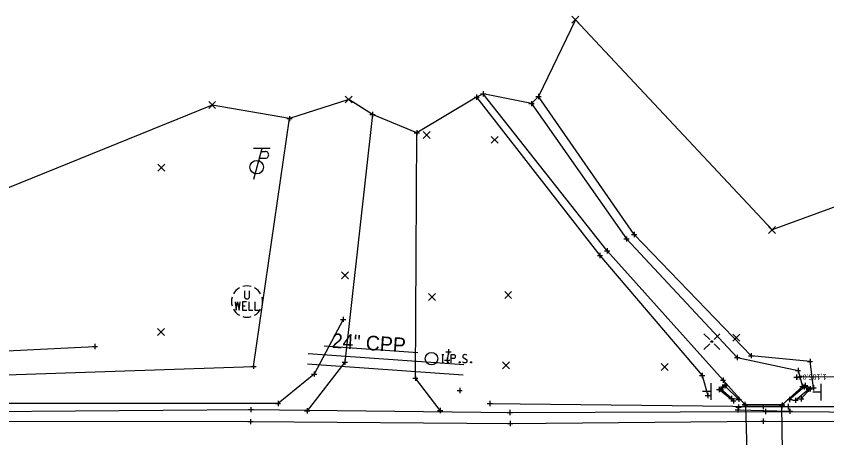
# Model space of a CAD drawing. Extents: x 2319153 to 2321514, y 575338 to 575500.
# Drawn here: x 2320670.1 to 2320825.9, y 575419.3 to 575500.3 of the extents above; entities that cross this region are included whole.
import ezdxf

# ---------------------------------------------------------------- set-up
doc = ezdxf.new("R2010")
doc.units = 0
for name, color, linetype in [('DR_X_Culvert', 7, 'Continuous'), ('DR_X_Ditch', 7, 'Continuous'), ('DR_X_Elev_Flow', 7, 'Continuous'), ('DR_X_Headwall', 7, 'Continuous'), ('DR_X_Storm_Sewer', 7, 'Continuous'), ('DR_X_Text', 7, 'Continuous'), ('PV_X_Driveway', 7, 'Continuous'), ('PV_X_EOP', 7, 'Continuous'), ('PV_X_Shoulder', 7, 'Continuous'), ('RD_X_GR_Lt', 7, 'Continuous'), ('RD_X_Wall', 7, 'Continuous'), ('SC_Scratch1', 7, 'Continuous'), ('SN_X_Public', 7, 'Continuous'), ('SV_P_Mon_Cells_Set', 7, 'Continuous'), ('SV_X_Break_Lines', 7, 'Continuous'), ('SV_X_Control_Cells_Found', 7, 'Continuous'), ('SV_X_Random_Point', 7, 'Continuous'), ('SV_X_Shot_Marker', 7, 'Continuous'), ('SV_X_Terrain_Boundary', 7, 'Continuous'), ('UT_X_Misc_Cells', 7, 'Continuous'), ('UT_X_Unknown_Cells', 7, 'Continuous')]:
    doc.layers.add(name, color=color, linetype=linetype)

msp = doc.modelspace()

# ---------------------------------------------------------------- linework, layer by layer
at = {"layer": 'DR_X_Culvert'}
msp.add_lwpolyline([(2320811.09, 575399.31), (2320817.7, 575399.29), (2320817.26, 575425.4), (2320810.29, 575425.41)], close=True, dxfattribs=at)
at = {"layer": 'DR_X_Ditch'}
for points in [[(2320769.15, 575483.51), (2320787.4, 575457.5), (2320808.68, 575434.74), (2320820.4, 575432.23), (2320821.28, 575429.18), (2320817.36, 575425.61), (2320810.18, 575425.69), (2320805.98, 575430.37), (2320783.69, 575455.23), (2320759.85, 575485.4)], [(2320442.27, 575427.97), (2320464.89, 575430.3), (2320567.27, 575429.23), (2320616.67, 575430.56), (2320664.25, 575431.29), (2320715.69, 575433.03), (2320722.62, 575480.62)]]:
    msp.add_lwpolyline(points, dxfattribs=at)
at = {"layer": 'DR_X_Elev_Flow'}
for p, q in [((2320820.1, 575431.46), (2320820.1, 575430.46)), ((2320819.6, 575430.96), (2320820.6, 575430.96)), ((2320820.1, 575430.96), (2320820.1, 575430.96))]:
    msp.add_line(p, q, dxfattribs=at)
at = {"layer": 'DR_X_Headwall'}
msp.add_lwpolyline([(2320808.96, 575425.17), (2320808.8, 575424.69), (2320818.83, 575424.39), (2320818.53, 575425.31)], close=True, dxfattribs=at)
at = {"layer": 'DR_X_Storm_Sewer'}
for p, q in [((2320756.14, 575433.31), (2320726.22, 575435.45)), ((2320756, 575431.31), (2320726.08, 575433.46)), ((2320984.73, 575431.64), (2320820.1, 575430.96))]:
    msp.add_line(p, q, dxfattribs=at)
at = {"layer": 'DR_X_Text'}
msp.add_line((2320747.27, 575435.6), (2320729.26, 575436.89), dxfattribs=at)
at = {"layer": 'PV_X_Driveway'}
for points in [[(2320738.56, 575481.4), (2320733.25, 575433.83), (2320725.99, 575424.49)], [(2320751.57, 575424.54), (2320746.81, 575430.73), (2320747.1, 575477.92)]]:
    msp.add_lwpolyline(points, dxfattribs=at)
at = {"layer": 'PV_X_EOP'}
msp.add_lwpolyline([(2320664.7, 575422.48), (2320715.11, 575422.41), (2320765.04, 575422.04), (2320813.73, 575422.51), (2320875.77, 575422.41), (2320913.27, 575422.56), (2320963.52, 575422.63), (2321012.62, 575422.4), (2321063.13, 575422.74), (2321112.87, 575422.46), (2321162.94, 575422.5), (2321212.67, 575422.22), (2321263.07, 575422.64), (2321312.9, 575422.52), (2321362.03, 575422.99), (2321412.61, 575423.24), (2321462.61, 575423.66), (2321512.13, 575424.2)], dxfattribs=at)
at = {"layer": 'PV_X_Shoulder'}
msp.add_lwpolyline([(2320664.52, 575424.33), (2320715.19, 575424.71), (2320764.98, 575424.15), (2320814.14, 575424.35), (2320863.42, 575424.12), (2320913.2, 575424.6), (2320963.28, 575424.88), (2321012.77, 575424.72), (2321063.18, 575424.45), (2321113.13, 575424.68), (2321162.73, 575424.41), (2321212.81, 575424.31), (2321262.9, 575424.09), (2321312.43, 575424.58), (2321362.34, 575425.06), (2321412.6, 575426.1), (2321462.14, 575426.29), (2321512.24, 575426.46)], dxfattribs=at)
at = {"layer": 'RD_X_GR_Lt'}
for p, q in [((2320753.17, 575435.82), (2320752.92, 575434.24)), ((2320761.13, 575425.9), (2320813.7, 575425.29)), ((2320813.7, 575425.29), (2320879.64, 575425.43))]:
    msp.add_line(p, q, dxfattribs=at)
at = {"layer": 'RD_X_Wall'}
for points in [[(2320809.02, 575426.68), (2320807.6, 575426.85), (2320805.56, 575428.66), (2320806.3, 575429.26)], [(2320818.79, 575426.67), (2320819.93, 575426.51), (2320822.44, 575428.64), (2320821.58, 575429.06)]]:
    msp.add_lwpolyline(points, close=True, dxfattribs=at)
at = {"layer": 'SN_X_Public'}
for p, q in [((2320803.63, 575429.77), (2320803.63, 575426.57)), ((2320824.82, 575429.65), (2320824.82, 575426.45)), ((2320803.63, 575428.17), (2320802.03, 575428.17)), ((2320824.82, 575428.05), (2320823.22, 575428.05))]:
    msp.add_line(p, q, dxfattribs=at)
at = {"layer": 'SV_P_Mon_Cells_Set'}
for points in [[(2320751.93, 575435.29), (2320752.28, 575435.29)], [(2320752.1, 575433.69), (2320752.1, 575435.29)], [(2320753.67, 575433.69), (2320753.67, 575435.29), (2320754.2, 575435.29), (2320754.25, 575435.28), (2320754.33, 575435.25), (2320754.36, 575435.23), (2320754.4, 575435.2), (2320754.44, 575435.14), (2320754.47, 575435.07), (2320754.5, 575434.97), (2320754.5, 575434.82), (2320754.49, 575434.77), (2320754.46, 575434.7), (2320754.42, 575434.61), (2320754.38, 575434.57), (2320754.34, 575434.55), (2320754.29, 575434.52), (2320754.2, 575434.51), (2320753.67, 575434.51)], [(2320756.68, 575435.18), (2320756.66, 575435.2), (2320756.62, 575435.23), (2320756.53, 575435.26), (2320756.4, 575435.29), (2320756.32, 575435.29), (2320756.28, 575435.29), (2320756.14, 575435.25), (2320756.02, 575435.18), (2320755.94, 575435.07), (2320755.92, 575434.97), (2320755.92, 575434.9), (2320755.94, 575434.8), (2320756.03, 575434.71), (2320756.64, 575434.33), (2320756.69, 575434.28), (2320756.71, 575434.23), (2320756.73, 575434.15), (2320756.73, 575434.08), (2320756.72, 575434), (2320756.71, 575433.95), (2320756.69, 575433.89), (2320756.67, 575433.84), (2320756.65, 575433.8), (2320756.61, 575433.76), (2320756.58, 575433.74), (2320756.54, 575433.71), (2320756.5, 575433.7), (2320756.4, 575433.69), (2320756.25, 575433.69), (2320756.15, 575433.71), (2320756.01, 575433.8), (2320755.92, 575433.88)], [(2320751.93, 575433.69), (2320752.28, 575433.69)], [(2320753.06, 575433.9), (2320753.12, 575433.9), (2320753.15, 575433.88), (2320753.19, 575433.83), (2320753.19, 575433.76), (2320753.15, 575433.71), (2320753.12, 575433.69), (2320753.06, 575433.69), (2320753.03, 575433.71), (2320753, 575433.76), (2320753, 575433.83), (2320753.03, 575433.88), (2320753.06, 575433.9)], [(2320755.31, 575433.9), (2320755.37, 575433.9), (2320755.4, 575433.88), (2320755.43, 575433.83), (2320755.43, 575433.76), (2320755.4, 575433.71), (2320755.37, 575433.69), (2320755.31, 575433.69), (2320755.28, 575433.71), (2320755.25, 575433.76), (2320755.25, 575433.83), (2320755.28, 575433.88), (2320755.31, 575433.9)], [(2320757.5, 575433.9), (2320757.55, 575433.9), (2320757.58, 575433.88), (2320757.62, 575433.83), (2320757.62, 575433.76), (2320757.58, 575433.71), (2320757.55, 575433.69), (2320757.5, 575433.69), (2320757.46, 575433.71), (2320757.43, 575433.76), (2320757.43, 575433.83), (2320757.46, 575433.88), (2320757.5, 575433.9)]]:
    msp.add_lwpolyline(points, dxfattribs=at)
msp.add_circle((2320749.91, 575434.49), 1.2, dxfattribs=at)
at = {"layer": 'SV_X_Break_Lines'}
for points in [[(2320758.6, 575484.73), (2320782.31, 575454.32), (2320801.95, 575431.28), (2320803.03, 575427.42)], [(2320823.37, 575428.92), (2320822.71, 575433.99), (2320811.41, 575435.08), (2320788.91, 575458.37), (2320770.49, 575484.86)], [(2320732.93, 575442.06), (2320727.34, 575431.55), (2320720.41, 575425.89), (2320664.7, 575425.9), (2320613.83, 575426.05), (2320563.12, 575426.93), (2320514.6, 575426.5), (2320463.64, 575427.26), (2320441.18, 575426.16), (2320442.02, 575430.24), (2320514.44, 575433.22), (2320564.58, 575433.19), (2320614.81, 575433.37), (2320685.2, 575436.83)], [(2320806.3, 575429.48), (2320805.21, 575428.58), (2320807.97, 575426.4)], [(2320821.01, 575426.77), (2320822.71, 575428.71), (2320821.78, 575429.37)]]:
    msp.add_lwpolyline(points, dxfattribs=at)
at = {"layer": 'SV_X_Control_Cells_Found'}
for p, q in [((2320802.32, 575439.28), (2320803.42, 575438.19)), ((2320804.25, 575438.19), (2320805.34, 575439.28)), ((2320802.32, 575436.26), (2320803.42, 575437.36)), ((2320804.25, 575437.36), (2320805.34, 575436.26))]:
    msp.add_line(p, q, dxfattribs=at)
msp.add_circle((2320803.83, 575437.78), 0.17, dxfattribs=at)
at = {"layer": 'SV_X_Random_Point'}
for p, q in [((2320776.92, 575498.97), (2320778.26, 575500.3)), ((2320776.92, 575500.3), (2320778.26, 575498.97)), ((2320733.34, 575483.63), (2320734.67, 575484.97)), ((2320733.34, 575484.97), (2320734.67, 575483.63)), ((2320707.07, 575482.57), (2320708.4, 575483.91)), ((2320707.07, 575483.91), (2320708.4, 575482.57)), ((2320748.33, 575476.81), (2320749.67, 575478.14)), ((2320748.33, 575478.14), (2320749.67, 575476.81)), ((2320761.39, 575475.88), (2320762.72, 575477.22)), ((2320761.39, 575477.22), (2320762.72, 575475.88)), ((2320697.32, 575470.53), (2320698.66, 575471.86)), ((2320697.32, 575471.86), (2320698.66, 575470.53)), ((2320814.75, 575458.56), (2320816.08, 575459.89)), ((2320814.75, 575459.89), (2320816.08, 575458.56)), ((2320732.61, 575449.83), (2320733.94, 575451.16)), ((2320732.61, 575451.16), (2320733.94, 575449.83)), ((2320749.37, 575445.67), (2320750.7, 575447.01)), ((2320749.37, 575447.01), (2320750.7, 575445.67)), ((2320763.99, 575446.05), (2320765.32, 575447.38)), ((2320763.99, 575447.38), (2320765.32, 575446.05)), ((2320697.23, 575438.96), (2320698.57, 575440.3)), ((2320697.23, 575440.3), (2320698.57, 575438.96)), ((2320807.87, 575437.88), (2320809.21, 575439.21)), ((2320807.87, 575439.21), (2320809.21, 575437.88)), ((2320763.59, 575432.58), (2320764.92, 575433.92)), ((2320763.59, 575433.92), (2320764.92, 575432.58)), ((2320794.08, 575432.23), (2320795.41, 575433.56)), ((2320794.08, 575433.56), (2320795.41, 575432.23))]:
    msp.add_line(p, q, dxfattribs=at)
at = {"layer": 'SV_X_Shot_Marker'}
for p, q in [((2320759.85, 575485.9), (2320759.85, 575484.9)), ((2320758.1, 575484.73), (2320759.1, 575484.73)), ((2320758.6, 575485.23), (2320758.6, 575484.23)), ((2320758.6, 575484.73), (2320758.6, 575484.73)), ((2320759.35, 575485.4), (2320760.35, 575485.4)), ((2320759.85, 575485.4), (2320759.85, 575485.4)), ((2320769.99, 575484.86), (2320770.99, 575484.86)), ((2320770.49, 575485.36), (2320770.49, 575484.36)), ((2320770.49, 575484.86), (2320770.49, 575484.86)), ((2320768.65, 575483.51), (2320769.65, 575483.51)), ((2320769.15, 575484.01), (2320769.15, 575483.01)), ((2320769.15, 575483.51), (2320769.15, 575483.51)), ((2320722.62, 575481.12), (2320722.62, 575480.12)), ((2320738.06, 575481.4), (2320739.06, 575481.4)), ((2320738.56, 575481.9), (2320738.56, 575480.9)), ((2320738.56, 575481.4), (2320738.56, 575481.4)), ((2320722.12, 575480.62), (2320723.12, 575480.62)), ((2320722.62, 575480.62), (2320722.62, 575480.62)), ((2320747.1, 575478.42), (2320747.1, 575477.42)), ((2320746.6, 575477.92), (2320747.6, 575477.92)), ((2320747.1, 575477.92), (2320747.1, 575477.92)), ((2320787.4, 575458), (2320787.4, 575457)), ((2320788.41, 575458.37), (2320789.41, 575458.37)), ((2320788.91, 575458.87), (2320788.91, 575457.87)), ((2320788.91, 575458.37), (2320788.91, 575458.37)), ((2320786.9, 575457.5), (2320787.9, 575457.5)), ((2320787.4, 575457.5), (2320787.4, 575457.5)), ((2320782.31, 575454.82), (2320782.31, 575453.82)), ((2320783.19, 575455.23), (2320784.19, 575455.23)), ((2320783.69, 575455.73), (2320783.69, 575454.73)), ((2320783.69, 575455.23), (2320783.69, 575455.23)), ((2320781.81, 575454.32), (2320782.81, 575454.32)), ((2320782.31, 575454.32), (2320782.31, 575454.32)), ((2320732.93, 575442.56), (2320732.93, 575441.56)), ((2320732.43, 575442.06), (2320733.43, 575442.06)), ((2320732.93, 575442.06), (2320732.93, 575442.06)), ((2320684.7, 575436.83), (2320685.7, 575436.83)), ((2320685.2, 575437.33), (2320685.2, 575436.33)), ((2320685.2, 575436.83), (2320685.2, 575436.83)), ((2320753.17, 575436.32), (2320753.17, 575435.32)), ((2320733.25, 575434.33), (2320733.25, 575433.33)), ((2320752.67, 575435.82), (2320753.67, 575435.82)), ((2320752.92, 575434.74), (2320752.92, 575433.74)), ((2320753.17, 575435.82), (2320753.17, 575435.82)), ((2320808.18, 575434.74), (2320809.18, 575434.74)), ((2320808.68, 575435.24), (2320808.68, 575434.24)), ((2320808.68, 575434.74), (2320808.68, 575434.74)), ((2320810.91, 575435.08), (2320811.91, 575435.08)), ((2320811.41, 575435.58), (2320811.41, 575434.58)), ((2320811.41, 575435.08), (2320811.41, 575435.08)), ((2320822.71, 575434.49), (2320822.71, 575433.49)), ((2320715.19, 575433.03), (2320716.19, 575433.03)), ((2320715.69, 575433.53), (2320715.69, 575432.53)), ((2320715.69, 575433.03), (2320715.69, 575433.03)), ((2320732.75, 575433.83), (2320733.75, 575433.83)), ((2320733.25, 575433.83), (2320733.25, 575433.83)), ((2320752.42, 575434.24), (2320753.42, 575434.24)), ((2320752.92, 575434.24), (2320752.92, 575434.24)), ((2320822.21, 575433.99), (2320823.21, 575433.99)), ((2320822.71, 575433.99), (2320822.71, 575433.99)), ((2320726.84, 575431.55), (2320727.84, 575431.55)), ((2320727.34, 575432.05), (2320727.34, 575431.05)), ((2320727.34, 575431.55), (2320727.34, 575431.55)), ((2320746.81, 575431.23), (2320746.81, 575430.23)), ((2320801.45, 575431.28), (2320802.45, 575431.28)), ((2320801.95, 575431.78), (2320801.95, 575430.78)), ((2320801.95, 575431.28), (2320801.95, 575431.28)), ((2320819.9, 575432.23), (2320820.9, 575432.23)), ((2320820.4, 575432.73), (2320820.4, 575431.73)), ((2320820.4, 575432.23), (2320820.4, 575432.23)), ((2320746.31, 575430.73), (2320747.31, 575430.73)), ((2320746.81, 575430.73), (2320746.81, 575430.73)), ((2320805.48, 575430.37), (2320806.48, 575430.37)), ((2320805.98, 575430.87), (2320805.98, 575429.87)), ((2320805.98, 575430.37), (2320805.98, 575430.37)), ((2320806.3, 575429.98), (2320806.3, 575428.98)), ((2320806.3, 575429.76), (2320806.3, 575428.76)), ((2320821.28, 575429.68), (2320821.28, 575428.68)), ((2320821.78, 575429.87), (2320821.78, 575428.87)), ((2320754.84, 575428.38), (2320755.84, 575428.38)), ((2320755.34, 575428.88), (2320755.34, 575427.88)), ((2320755.34, 575428.38), (2320755.34, 575428.38)), ((2320804.71, 575428.58), (2320805.71, 575428.58)), ((2320805.06, 575428.66), (2320806.06, 575428.66)), ((2320805.21, 575429.08), (2320805.21, 575428.08)), ((2320805.21, 575428.58), (2320805.21, 575428.58)), ((2320805.56, 575429.16), (2320805.56, 575428.16)), ((2320805.56, 575428.66), (2320805.56, 575428.66)), ((2320805.8, 575429.48), (2320806.8, 575429.48)), ((2320805.8, 575429.26), (2320806.8, 575429.26)), ((2320806.3, 575429.48), (2320806.3, 575429.48)), ((2320806.3, 575429.26), (2320806.3, 575429.26)), ((2320820.78, 575429.18), (2320821.78, 575429.18)), ((2320821.08, 575429.06), (2320822.08, 575429.06)), ((2320821.28, 575429.37), (2320822.28, 575429.37)), ((2320821.28, 575429.18), (2320821.28, 575429.18)), ((2320821.58, 575429.56), (2320821.58, 575428.56)), ((2320821.58, 575429.06), (2320821.58, 575429.06)), ((2320821.78, 575429.37), (2320821.78, 575429.37)), ((2320821.94, 575428.64), (2320822.94, 575428.64)), ((2320822.21, 575428.71), (2320823.21, 575428.71)), ((2320822.44, 575429.14), (2320822.44, 575428.14)), ((2320822.44, 575428.64), (2320822.44, 575428.64)), ((2320822.71, 575429.21), (2320822.71, 575428.21)), ((2320822.71, 575428.71), (2320822.71, 575428.71)), ((2320822.87, 575428.92), (2320823.87, 575428.92)), ((2320823.37, 575429.42), (2320823.37, 575428.42)), ((2320823.37, 575428.92), (2320823.37, 575428.92)), ((2320802.53, 575427.42), (2320803.53, 575427.42)), ((2320803.03, 575427.92), (2320803.03, 575426.92)), ((2320803.03, 575427.42), (2320803.03, 575427.42)), ((2320807.1, 575426.85), (2320808.1, 575426.85)), ((2320807.6, 575427.35), (2320807.6, 575426.35)), ((2320807.6, 575426.85), (2320807.6, 575426.85)), ((2320807.97, 575426.9), (2320807.97, 575425.9)), ((2320808.52, 575426.68), (2320809.52, 575426.68)), ((2320809.02, 575427.18), (2320809.02, 575426.18)), ((2320809.02, 575426.68), (2320809.02, 575426.68)), ((2320818.29, 575426.67), (2320819.29, 575426.67)), ((2320818.79, 575427.17), (2320818.79, 575426.17)), ((2320818.79, 575426.67), (2320818.79, 575426.67)), ((2320819.93, 575427.01), (2320819.93, 575426.01)), ((2320820.51, 575426.77), (2320821.51, 575426.77)), ((2320821.01, 575427.27), (2320821.01, 575426.27)), ((2320821.01, 575426.77), (2320821.01, 575426.77)), ((2320715.19, 575425.21), (2320715.19, 575424.21)), ((2320719.91, 575425.89), (2320720.91, 575425.89)), ((2320720.41, 575426.39), (2320720.41, 575425.39)), ((2320720.41, 575425.89), (2320720.41, 575425.89)), ((2320725.99, 575424.99), (2320725.99, 575423.99)), ((2320751.57, 575425.04), (2320751.57, 575424.04)), ((2320760.63, 575425.9), (2320761.63, 575425.9)), ((2320761.13, 575426.4), (2320761.13, 575425.4)), ((2320761.13, 575425.9), (2320761.13, 575425.9)), ((2320807.47, 575426.4), (2320808.47, 575426.4)), ((2320807.97, 575426.4), (2320807.97, 575426.4)), ((2320808.46, 575425.17), (2320809.46, 575425.17)), ((2320808.8, 575425.19), (2320808.8, 575424.19)), ((2320808.96, 575425.67), (2320808.96, 575424.67)), ((2320808.96, 575425.17), (2320808.96, 575425.17)), ((2320809.68, 575425.69), (2320810.68, 575425.69)), ((2320809.79, 575425.41), (2320810.79, 575425.41)), ((2320810.18, 575426.19), (2320810.18, 575425.19)), ((2320810.18, 575425.69), (2320810.18, 575425.69)), ((2320810.29, 575425.91), (2320810.29, 575424.91)), ((2320810.29, 575425.41), (2320810.29, 575425.41)), ((2320813.2, 575425.29), (2320814.2, 575425.29)), ((2320813.7, 575425.79), (2320813.7, 575424.79)), ((2320813.7, 575425.29), (2320813.7, 575425.29)), ((2320816.76, 575425.4), (2320817.76, 575425.4)), ((2320816.86, 575425.61), (2320817.86, 575425.61)), ((2320817.26, 575425.9), (2320817.26, 575424.9)), ((2320817.26, 575425.4), (2320817.26, 575425.4)), ((2320817.36, 575426.11), (2320817.36, 575425.11)), ((2320817.36, 575425.61), (2320817.36, 575425.61)), ((2320818.03, 575425.31), (2320819.03, 575425.31)), ((2320818.53, 575425.81), (2320818.53, 575424.81)), ((2320818.53, 575425.31), (2320818.53, 575425.31)), ((2320819.43, 575426.51), (2320820.43, 575426.51)), ((2320819.93, 575426.51), (2320819.93, 575426.51)), ((2320714.69, 575424.71), (2320715.69, 575424.71)), ((2320715.19, 575424.71), (2320715.19, 575424.71)), ((2320725.49, 575424.49), (2320726.49, 575424.49)), ((2320725.99, 575424.49), (2320725.99, 575424.49)), ((2320751.07, 575424.54), (2320752.07, 575424.54)), ((2320751.57, 575424.54), (2320751.57, 575424.54)), ((2320764.48, 575424.15), (2320765.48, 575424.15)), ((2320764.98, 575424.65), (2320764.98, 575423.65)), ((2320764.98, 575424.15), (2320764.98, 575424.15)), ((2320808.3, 575424.69), (2320809.3, 575424.69)), ((2320808.8, 575424.69), (2320808.8, 575424.69)), ((2320813.64, 575424.35), (2320814.64, 575424.35)), ((2320814.14, 575424.85), (2320814.14, 575423.85)), ((2320814.14, 575424.35), (2320814.14, 575424.35)), ((2320818.33, 575424.39), (2320819.33, 575424.39)), ((2320818.83, 575424.89), (2320818.83, 575423.89)), ((2320818.83, 575424.39), (2320818.83, 575424.39)), ((2320714.61, 575422.41), (2320715.61, 575422.41)), ((2320715.11, 575422.91), (2320715.11, 575421.91)), ((2320715.11, 575422.41), (2320715.11, 575422.41)), ((2320764.54, 575422.04), (2320765.54, 575422.04)), ((2320765.04, 575422.54), (2320765.04, 575421.54)), ((2320765.04, 575422.04), (2320765.04, 575422.04)), ((2320813.23, 575422.51), (2320814.23, 575422.51)), ((2320813.73, 575423.01), (2320813.73, 575422.01)), ((2320813.73, 575422.51), (2320813.73, 575422.51))]:
    msp.add_line(p, q, dxfattribs=at)
at = {"layer": 'SV_X_Terrain_Boundary'}
msp.add_lwpolyline([(2321262.9, 575424.09), (2321213.75, 575454.03), (2321174.26, 575455.72), (2321165.44, 575454.44), (2321113.51, 575450.31), (2321063.39, 575450.45), (2321013.2, 575451.03), (2320972.82, 575455.47), (2320964.59, 575452.67), (2320952.83, 575453.45), (2320913.64, 575458.23), (2320857.66, 575474.67), (2320815.41, 575459.23), (2320777.59, 575499.63), (2320770.49, 575484.86), (2320769.15, 575483.51), (2320759.85, 575485.4), (2320758.6, 575484.73), (2320747.1, 575477.92), (2320738.56, 575481.4), (2320734.01, 575484.3), (2320722.62, 575480.62), (2320707.74, 575483.24), (2320663.9, 575465.47)], dxfattribs=at)
at = {"layer": 'UT_X_Misc_Cells'}
for p, q in [((2320717.28, 575474.9), (2320715.67, 575468.9)), ((2320718.88, 575474.9), (2320715.68, 575474.9)), ((2320717.12, 575474.3), (2320717.97, 575474.3)), ((2320716.78, 575473.02), (2320717.97, 575473.02))]:
    msp.add_line(p, q, dxfattribs=at)
msp.add_circle((2320716.31, 575471.3), 1.3, dxfattribs=at)
msp.add_arc((2320717.98, 575473.66), 0.638, 268.8767, 91.1233, dxfattribs=at)
at = {"layer": 'UT_X_Unknown_Cells'}
msp.add_line((2320714.44, 575445.48), (2320714.44, 575445.48), dxfattribs=at)
for points in [[(2320713.96, 575447.57), (2320713.96, 575446.45), (2320713.98, 575446.34), (2320713.99, 575446.3), (2320714.01, 575446.24), (2320714.04, 575446.19), (2320714.08, 575446.14), (2320714.1, 575446.11), (2320714.12, 575446.1), (2320714.17, 575446.06), (2320714.2, 575446.03), (2320714.25, 575446.01), (2320714.33, 575445.98), (2320714.4, 575445.97), (2320714.48, 575445.97), (2320714.56, 575445.98), (2320714.61, 575446), (2320714.68, 575446.03), (2320714.74, 575446.07), (2320714.8, 575446.12), (2320714.85, 575446.19), (2320714.88, 575446.26), (2320714.91, 575446.32), (2320714.92, 575446.45), (2320714.92, 575447.57)], [(2320712.15, 575445.45), (2320712.36, 575443.85), (2320712.63, 575445.45), (2320712.91, 575443.85), (2320713.13, 575445.45)], [(2320714.33, 575445.45), (2320713.57, 575445.45), (2320713.57, 575443.85), (2320714.39, 575443.85)], [(2320714.77, 575445.45), (2320714.77, 575443.85), (2320715.53, 575443.85)], [(2320715.97, 575445.45), (2320715.97, 575443.85), (2320716.74, 575443.85)], [(2320713.57, 575444.66), (2320714.11, 575444.66)]]:
    msp.add_lwpolyline(points, dxfattribs=at)
for start, end in [(73.9409, 105.9366), (118.9866, 150.9578), (28.9866, 60.9578), (164.0021, 196.0591), (344.0021, 15.9979), (208.9866, 240.9578), (298.9866, 331.0134), (253.9409, 285.9366)]:
    msp.add_arc((2320714.44, 575445.48), 3, start, end, dxfattribs=at)

# ---------------------------------------------------------------- texts
at = {"layer": 'DR_X_Text'}
msp.add_text('24" CPP', height=2.8, rotation=356.3767, dxfattribs=at).set_placement((2320730.69, 575436.6))
at = {"layer": 'SC_Scratch1'}
msp.add_text("1,185.04'", height=1, rotation=180.2376, dxfattribs=at).set_placement((2320825.88, 575431.48))

doc.saveas('drawing.dxf')
